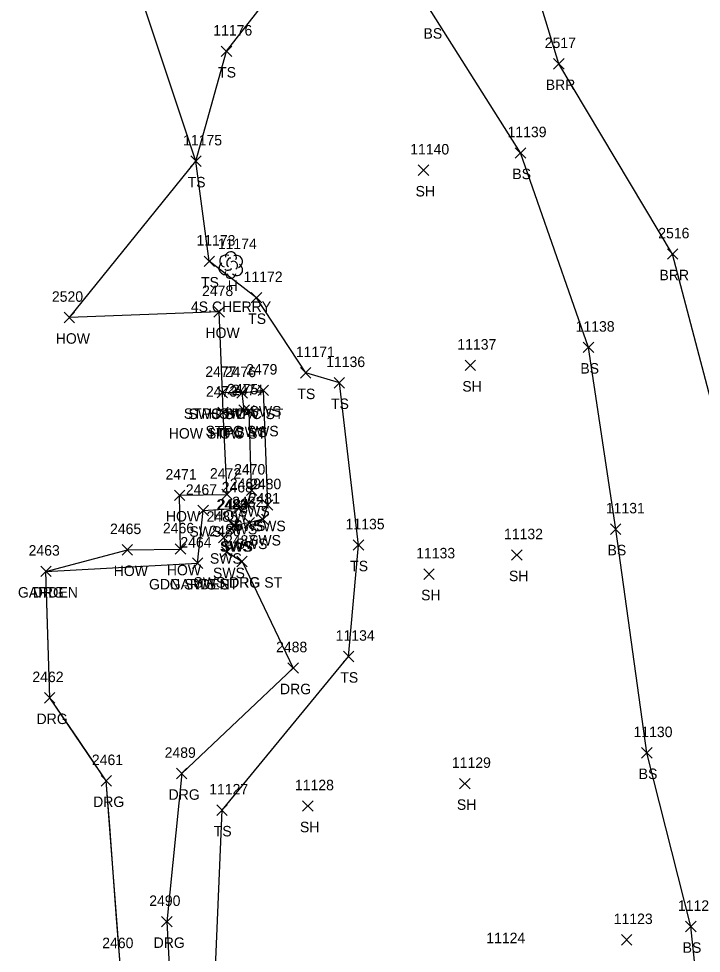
# Model space of a CAD drawing. Extents: x 1439173 to 1457902, y 641926 to 659889.
# Drawn here: x 1447787.4 to 1447917.7, y 648142.7 to 648320.9 of the extents above; entities that cross this region are included whole.
import ezdxf

# ---------------------------------------------------------------- set-up
doc = ezdxf.new("R2010")
doc.units = 0
for name, color, linetype in [('L_A', 7, 'Continuous'), ('L_C', 7, 'Continuous'), ('L_I', 7, 'Continuous'), ('L_TIC', 7, 'Continuous'), ('LABL', 7, 'Continuous'), ('LAPB', 7, 'Continuous'), ('LBC', 7, 'Continuous'), ('LBF', 7, 'Continuous'), ('LELB', 7, 'Continuous'), ('LSOGP', 7, 'Continuous'), ('LTD', 7, 'Continuous'), ('R_A', 7, 'Continuous'), ('R_I', 7, 'Continuous'), ('R_TIC', 7, 'Continuous'), ('RDG', 7, 'Continuous'), ('RSW', 7, 'Continuous')]:
    doc.layers.add(name, color=color, linetype=linetype)

msp = doc.modelspace()

# ---------------------------------------------------------------- linework, layer by layer
at = {"layer": 'L_TIC'}
for points in [[(1447826.09, 648313.7), (1447828.09, 648315.7)], [(1447828.09, 648313.7), (1447826.09, 648315.7)], [(1447889.52, 648311.32), (1447891.52, 648313.32)], [(1447891.52, 648311.32), (1447889.52, 648313.32)], [(1447882.2, 648294.32), (1447884.2, 648296.32)], [(1447884.2, 648294.32), (1447882.2, 648296.32)], [(1447820.27, 648292.75), (1447822.27, 648294.75)], [(1447822.27, 648292.75), (1447820.27, 648294.75)], [(1447863.69, 648291.02), (1447865.69, 648293.02)], [(1447865.69, 648291.02), (1447863.69, 648293.02)], [(1447911.22, 648275.03), (1447913.22, 648277.03)], [(1447913.22, 648275.03), (1447911.22, 648277.03)], [(1447822.82, 648273.65), (1447824.82, 648275.65)], [(1447824.82, 648273.65), (1447822.82, 648275.65)], [(1447831.83, 648266.7), (1447833.83, 648268.7)], [(1447833.83, 648266.7), (1447831.83, 648268.7)], [(1447796.13, 648262.93), (1447798.13, 648264.93)], [(1447798.13, 648262.93), (1447796.13, 648264.93)], [(1447824.7, 648264.02), (1447826.7, 648266.02)], [(1447826.7, 648264.02), (1447824.7, 648266.02)], [(1447895.17, 648257.23), (1447897.17, 648259.23)], [(1447897.17, 648257.23), (1447895.17, 648259.23)], [(1447872.61, 648253.81), (1447874.61, 648255.81)], [(1447874.61, 648253.81), (1447872.61, 648255.81)], [(1447841.22, 648252.37), (1447843.22, 648254.37)], [(1447843.22, 648252.37), (1447841.22, 648254.37)], [(1447847.64, 648250.48), (1447849.64, 648252.48)], [(1447849.64, 648250.48), (1447847.64, 648252.48)], [(1447825.32, 648248.61), (1447827.32, 648250.61)], [(1447827.32, 648248.61), (1447825.32, 648250.61)], [(1447825.32, 648248.61), (1447827.32, 648250.61)], [(1447827.32, 648248.61), (1447825.32, 648250.61)], [(1447829.1, 648248.56), (1447831.1, 648250.56)], [(1447831.1, 648248.56), (1447829.1, 648250.56)], [(1447825.45, 648244.84), (1447827.45, 648246.84)], [(1447827.45, 648244.84), (1447825.45, 648246.84)], [(1447825.45, 648244.84), (1447827.45, 648246.84)], [(1447827.45, 648244.84), (1447825.45, 648246.84)], [(1447829.47, 648245.27), (1447831.47, 648247.27)], [(1447831.47, 648245.27), (1447829.47, 648247.27)], [(1447817.15, 648229.03), (1447819.15, 648231.03)], [(1447819.15, 648229.03), (1447817.15, 648231.03)], [(1447826.2, 648229.2), (1447828.2, 648231.2)], [(1447828.2, 648229.2), (1447826.2, 648231.2)], [(1447900.37, 648222.58), (1447902.37, 648224.58)], [(1447902.37, 648222.58), (1447900.37, 648224.58)], [(1447807.19, 648218.63), (1447809.19, 648220.63)], [(1447809.19, 648218.63), (1447807.19, 648220.63)], [(1447817.33, 648218.77), (1447819.33, 648220.77)], [(1447819.33, 648218.77), (1447817.33, 648220.77)], [(1447851.29, 648219.54), (1447853.29, 648221.54)], [(1447853.29, 648219.54), (1447851.29, 648221.54)], [(1447881.51, 648217.65), (1447883.51, 648219.65)], [(1447883.51, 648217.65), (1447881.51, 648219.65)], [(1447791.65, 648214.52), (1447793.65, 648216.52)], [(1447793.65, 648214.52), (1447791.65, 648216.52)], [(1447820.6, 648216.07), (1447822.6, 648218.07)], [(1447822.6, 648216.07), (1447820.6, 648218.07)], [(1447864.75, 648214), (1447866.75, 648216)], [(1447866.75, 648214), (1447864.75, 648216)], [(1447849.4, 648198.29), (1447851.4, 648200.29)], [(1447851.4, 648198.29), (1447849.4, 648200.29)], [(1447906.31, 648179.91), (1447908.31, 648181.91)], [(1447908.31, 648179.91), (1447906.31, 648181.91)], [(1447871.57, 648174.04), (1447873.57, 648176.04)], [(1447873.57, 648174.04), (1447871.57, 648176.04)], [(1447825.26, 648168.98), (1447827.26, 648170.98)], [(1447827.26, 648168.98), (1447825.26, 648170.98)], [(1447841.62, 648169.77), (1447843.62, 648171.77)], [(1447843.62, 648169.77), (1447841.62, 648171.77)], [(1447914.7, 648146.78), (1447916.7, 648148.78)], [(1447916.7, 648146.78), (1447914.7, 648148.78)], [(1447902.45, 648144.26), (1447904.45, 648146.26)], [(1447904.45, 648144.26), (1447902.45, 648146.26)]]:
    msp.add_lwpolyline(points, dxfattribs=at)
at = {"layer": 'LABL'}
msp.add_lwpolyline([(1447975.52, 648148.69), (1447981.52, 648110.97), (1447974.2, 648092.22), (1447958.64, 648075.67), (1447941.87, 648100.07), (1447936.57, 648139.24), (1447926.83, 648188.41), (1447923.24, 648233.98), (1447912.22, 648276.03), (1447890.52, 648312.32), (1447885.31, 648329.49), (1447844.46, 648358.6), (1447883.24, 648371.65), (1447915.86, 648376.25), (1447938.91, 648380.03), (1447948.39, 648332.97), (1447948.3, 648332.92), (1447954.84, 648284.4)], dxfattribs=at)
at = {"layer": 'LAPB'}
msp.add_lwpolyline([(1447792.65, 648215.52), (1447821.6, 648217.07)], dxfattribs=at)
at = {"layer": 'LBC'}
msp.add_lwpolyline([(1447808.19, 648219.63), (1447818.33, 648219.77), (1447818.15, 648230.03), (1447827.2, 648230.2), (1447826.45, 648245.84), (1447826.32, 648249.61), (1447825.7, 648265.02), (1447797.13, 648263.93)], dxfattribs=at)
at = {"layer": 'LBF'}
for points in [[(1447830.1, 648249.56), (1447826.32, 648249.61)], [(1447826.45, 648245.84), (1447830.47, 648246.27)]]:
    msp.add_lwpolyline(points, dxfattribs=at)
at = {"layer": 'LELB'}
for points in [[(1447948.66, 648059.36), (1447926.41, 648053.33), (1447891.46, 648047.11), (1447863.43, 648042.99), (1447838.8, 648055.7), (1447830.08, 648068.33), (1447823.25, 648098.35), (1447824.6, 648130.92), (1447826.26, 648169.98), (1447850.4, 648199.29), (1447852.29, 648220.54), (1447848.64, 648251.48), (1447842.22, 648253.37), (1447832.83, 648267.7), (1447823.82, 648274.65), (1447821.27, 648293.75), (1447827.09, 648314.7), (1447838.18, 648328.91), (1447846.62, 648343.8), (1447843.4, 648351.49), (1447804.36, 648349.3)], [(1447925.77, 648058.24), (1447929.14, 648088.66), (1447919.16, 648115.38), (1447915.7, 648147.78), (1447907.31, 648180.91), (1447901.37, 648223.58), (1447896.17, 648258.23), (1447883.2, 648295.32), (1447866.25, 648322.11), (1447854.43, 648340.12), (1447846.62, 648343.8), (1447805.14, 648342.06)]]:
    msp.add_lwpolyline(points, dxfattribs=at)
at = {"layer": 'LSOGP'}
msp.add_lwpolyline([(1447806.79, 648140.65), (1447806.13, 648149.38), (1447805.48, 648158.11), (1447804.82, 648166.84), (1447804.17, 648175.57), (1447798.77, 648183.49), (1447793.37, 648191.4), (1447793.19, 648197.43), (1447793.01, 648203.46), (1447792.82, 648209.49), (1447792.64, 648215.52), (1447808.19, 648219.63), (1447818.33, 648219.77), (1447818.15, 648230.04), (1447827.2, 648230.2), (1447826.46, 648245.83), (1447826.32, 648249.62), (1447825.7, 648265.01), (1447797.13, 648263.93), (1447821.27, 648293.77), (1447805.14, 648342.09)], dxfattribs=at)
at = {"layer": 'LTD'}
msp.add_line((1447827.9, 648273.99), (1447827.9, 648273.99), dxfattribs=at)
msp.add_line((1447827.9, 648273.99), (1447827.9, 648273.99), dxfattribs=at)
msp.add_arc((1447827.94, 648275.43), 1.05, 335.5272, 180.9563, dxfattribs=at)
for centre, major_axis, ratio, start_param, end_param in [((1447827.1, 648274.66), (1.21, -0.51), 0.895232, 1.570796, 4.712389), ((1447827.69, 648274.45), (-0.208, -0.792), 0.645439, 3.141593, 6.283185), ((1447828.94, 648274.58), (-1.14, -0.48), 0.949671, 1.570796, 4.712389), ((1447826.81, 648273.28), (0.58, -1.04), 0.959034, 3.141593, 6.283185), ((1447828.4, 648273.83), (-0.5, 0.667), 0.989748, 3.141593, 6.283185), ((1447828.9, 648273.16), (-1.09, 0.79), 0.841452, 1.570796, 4.712389), ((1447827.9, 648272.49), (0.26, 1.06), 0.942809, 1.570796, 4.712389), ((1447827.44, 648273.24), (-0.625, -0.083), 0.423636, 0, 3.141593)]:
    msp.add_ellipse(centre, major_axis=major_axis, ratio=ratio, start_param=start_param, end_param=end_param, dxfattribs=at)
at = {"layer": 'R_TIC'}
for points in [[(1447829.1, 648248.56), (1447831.1, 648250.56)], [(1447831.1, 648248.56), (1447829.1, 648250.56)], [(1447833.13, 648249.05), (1447835.13, 648251.05)], [(1447835.13, 648249.05), (1447833.13, 648251.05)], [(1447829.47, 648245.27), (1447831.47, 648247.27)], [(1447831.47, 648245.27), (1447829.47, 648247.27)], [(1447830.41, 648245.12), (1447832.41, 648247.12)], [(1447832.41, 648245.12), (1447830.41, 648247.12)], [(1447830.9, 648229.98), (1447832.9, 648231.98)], [(1447832.9, 648229.98), (1447830.9, 648231.98)], [(1447830.06, 648227.23), (1447832.06, 648229.23)], [(1447832.06, 648227.23), (1447830.06, 648229.23)], [(1447833.94, 648227.18), (1447835.94, 648229.18)], [(1447835.94, 648227.18), (1447833.94, 648229.18)], [(1447821.65, 648226.12), (1447823.65, 648228.12)], [(1447823.65, 648226.12), (1447821.65, 648228.12)], [(1447828.51, 648226.58), (1447830.51, 648228.58)], [(1447830.51, 648226.58), (1447828.51, 648228.58)], [(1447827.45, 648223.27), (1447829.45, 648225.27)], [(1447829.45, 648223.27), (1447827.45, 648225.27)], [(1447827.68, 648223.29), (1447829.68, 648225.29)], [(1447829.68, 648223.29), (1447827.68, 648225.29)], [(1447830.45, 648223.77), (1447832.45, 648225.77)], [(1447832.45, 648223.77), (1447830.45, 648225.77)], [(1447833.03, 648224.45), (1447835.03, 648226.45)], [(1447835.03, 648224.45), (1447833.03, 648226.45)], [(1447825.57, 648220.98), (1447827.57, 648222.98)], [(1447827.57, 648220.98), (1447825.57, 648222.98)], [(1447826.15, 648218.22), (1447828.15, 648220.22)], [(1447828.15, 648218.22), (1447826.15, 648220.22)], [(1447829.07, 648216.41), (1447831.07, 648218.41)], [(1447831.07, 648216.41), (1447829.07, 648218.41)], [(1447829.07, 648216.41), (1447831.07, 648218.41)], [(1447831.07, 648216.41), (1447829.07, 648218.41)], [(1447791.65, 648214.52), (1447793.65, 648216.52)], [(1447793.65, 648214.52), (1447791.65, 648216.52)], [(1447820.6, 648216.07), (1447822.6, 648218.07)], [(1447822.6, 648216.07), (1447820.6, 648218.07)], [(1447838.82, 648196.09), (1447840.82, 648198.09)], [(1447840.82, 648196.09), (1447838.82, 648198.09)], [(1447792.37, 648190.4), (1447794.37, 648192.4)], [(1447794.37, 648190.4), (1447792.37, 648192.4)], [(1447817.56, 648175.96), (1447819.56, 648177.96)], [(1447819.56, 648175.96), (1447817.56, 648177.96)], [(1447803.16, 648174.58), (1447805.16, 648176.58)], [(1447805.16, 648174.58), (1447803.16, 648176.58)], [(1447814.71, 648147.71), (1447816.71, 648149.71)], [(1447816.71, 648147.71), (1447814.71, 648149.71)]]:
    msp.add_lwpolyline(points, dxfattribs=at)
at = {"layer": 'RDG'}
for points in [[(1447830.07, 648217.41), (1447839.82, 648197.09), (1447818.56, 648176.96), (1447815.71, 648148.71), (1447817.42, 648116.7), (1447817.39, 648116.66), (1447822.31, 648081.99), (1447826.74, 648066.41), (1447833.19, 648054.59), (1447847.63, 648042.87), (1447857.73, 648041.17), (1447891.19, 648045.8), (1447923.48, 648050.8), (1447947.17, 648055.37), (1447974.14, 648064.54)], [(1447814.09, 648028.59), (1447824.25, 648033.86), (1447821.06, 648054.4), (1447812.57, 648078.1), (1447812.73, 648078.08), (1447808.88, 648103.1), (1447806.79, 648140.66), (1447804.16, 648175.58), (1447793.37, 648191.4), (1447792.65, 648215.52)]]:
    msp.add_lwpolyline(points, dxfattribs=at)
at = {"layer": 'RSW'}
msp.add_lwpolyline([(1447821.6, 648217.07), (1447822.65, 648227.12), (1447829.51, 648227.58), (1447831.06, 648228.23), (1447831.9, 648230.98), (1447831.41, 648246.12), (1447830.47, 648246.27), (1447830.1, 648249.56), (1447834.13, 648250.05), (1447834.94, 648228.18), (1447834.03, 648225.45), (1447831.45, 648224.77), (1447828.45, 648224.27), (1447828.68, 648224.29), (1447826.57, 648221.98), (1447827.15, 648219.22), (1447830.07, 648217.41)], dxfattribs=at)

# ---------------------------------------------------------------- texts
at = {"layer": 'L_A'}
for s, p in [('BS', (1447864.69, 648317.11)), ('TS', (1447825.5, 648309.7)), ('BRR', (1447888.01, 648307.32)), ('BS', (1447881.64, 648290.32)), ('TS', (1447819.68, 648288.75)), ('SH', (1447863.18, 648287.02)), ('TS', (1447822.23, 648269.65)), ('BRR', (1447909.71, 648271.03)), ('H', (1447827.33, 648268.99)), ('TS', (1447831.24, 648262.7)), ('HOW', (1447794.52, 648258.93)), ('HOW', (1447823.09, 648260.02)), ('BS', (1447894.62, 648253.23)), ('TS', (1447840.63, 648248.37)), ('SH', (1447872.1, 648249.81)), ('TS', (1447847.04, 648246.48)), ('STPC HOW', (1447818.95, 648244.61)), ('SWS STPC ST', (1447819.84, 648244.56)), ('HOW', (1447823.7, 648244.61)), ('STPC SWS', (1447823.09, 648241.27)), ('HOW STPC ST', (1447816.08, 648240.84)), ('HOW', (1447823.84, 648240.84)), ('HOW', (1447815.54, 648225.03)), ('HOW', (1447824.58, 648225.2)), ('BS', (1447899.81, 648218.58)), ('HOW', (1447805.58, 648214.63)), ('HOW', (1447815.72, 648214.77)), ('TS', (1447850.7, 648215.54)), ('SH', (1447881, 648213.65)), ('GARDEN', (1447816.27, 648212.07)), ('GARDEN', (1447787.31, 648210.52)), ('SH', (1447864.24, 648210)), ('TS', (1447848.81, 648194.29)), ('BS', (1447905.75, 648175.91)), ('SH', (1447871.06, 648170.04)), ('TS', (1447824.67, 648164.98)), ('SH', (1447841.11, 648165.77)), ('BS', (1447914.14, 648142.78))]:
    msp.add_text(s, height=2, dxfattribs=at).set_placement(p)
at = {"layer": 'L_C'}
msp.add_text('4S.CHERRY', height=2, dxfattribs=at).set_placement((1447820.31, 648264.99))
at = {"layer": 'L_I'}
for s, p in [('11176', (1447824.58, 648317.7)), ('2517', (1447887.83, 648315.32)), ('11139', (1447880.73, 648298.32)), ('11175', (1447818.82, 648296.75)), ('11140', (1447862.15, 648295.02)), ('2516', (1447909.48, 648279.03)), ('11173', (1447821.37, 648277.65)), ('11174', (1447825.44, 648276.99)), ('11172', (1447830.37, 648270.7)), ('2478', (1447822.44, 648268.02)), ('2520', (1447793.79, 648266.93)), ('11138', (1447893.72, 648261.23)), ('11137', (1447871.15, 648257.81)), ('11171', (1447840.33, 648256.37)), ('11136', (1447846.12, 648254.48)), ('2477', (1447823.06, 648252.61)), ('2477', (1447823.06, 648252.61)), ('2476', (1447826.78, 648252.56)), ('2473', (1447823.19, 648248.84)), ('2473', (1447823.19, 648248.84)), ('2475', (1447827.21, 648249.27)), ('2471', (1447815.46, 648233.03)), ('2472', (1447823.94, 648233.2)), ('11131', (1447899.48, 648226.58)), ('11135', (1447849.83, 648223.54)), ('2465', (1447804.88, 648222.63)), ('2466', (1447814.97, 648222.77)), ('11132', (1447880.05, 648221.65)), ('2464', (1447818.3, 648220.07)), ('2463', (1447789.34, 648218.52)), ('11133', (1447863.29, 648218)), ('11134', (1447847.94, 648202.29)), ('11130', (1447904.76, 648183.91)), ('11129', (1447870.11, 648178.04)), ('11128', (1447840.16, 648173.77)), ('11127', (1447823.8, 648172.98)), ('11122', (1447913.24, 648150.78)), ('11123', (1447900.99, 648148.26)), ('11124', (1447876.67, 648144.61))]:
    msp.add_text(s, height=2, dxfattribs=at).set_placement(p)
at = {"layer": 'R_A'}
for s, p in [('SWS', (1447831.5, 648245.05)), ('SWS STPC ST', (1447819.84, 648244.56)), ('STPC SWS', (1447823.09, 648241.27)), ('SWS', (1447828.78, 648241.12)), ('SWS', (1447829.27, 648225.98)), ('SWS', (1447828.43, 648223.23)), ('SWS', (1447820.02, 648222.12)), ('SWS', (1447826.88, 648222.58)), ('SWS', (1447832.31, 648223.18)), ('SWS', (1447828.82, 648219.77)), ('SWS', (1447831.4, 648220.45)), ('SWS', (1447825.82, 648219.27)), ('SWS', (1447826.05, 648219.29)), ('SWS', (1447823.94, 648216.98)), ('SWS', (1447824.52, 648214.22)), ('GDN SWS ST', (1447812.32, 648212.07)), ('SWS DRG ST', (1447820.79, 648212.41)), ('DRG', (1447827.56, 648212.41)), ('DRG', (1447790.13, 648210.52)), ('DRG', (1447837.31, 648192.09)), ('DRG', (1447790.86, 648186.4)), ('DRG', (1447816.05, 648171.96)), ('DRG', (1447801.65, 648170.58)), ('DRG', (1447813.2, 648143.71))]:
    msp.add_text(s, height=2, dxfattribs=at).set_placement(p)
at = {"layer": 'R_I'}
for s, p in [('2476', (1447826.78, 648252.56)), ('2479', (1447830.86, 648253.05)), ('2475', (1447827.21, 648249.27)), ('2474', (1447828.15, 648249.12)), ('2470', (1447828.56, 648233.98)), ('2468', (1447826.2, 648230.58)), ('2469', (1447827.74, 648231.23)), ('2480', (1447831.6, 648231.18)), ('2467', (1447819.34, 648230.12)), ('2483', (1447825.19, 648227.27)), ('2484', (1447825.42, 648227.29)), ('2482', (1447828.19, 648227.77)), ('2481', (1447831.34, 648228.45)), ('2485', (1447823.31, 648224.98)), ('2486', (1447823.84, 648222.22)), ('2464', (1447818.3, 648220.07)), ('2487', (1447826.81, 648220.41)), ('2487', (1447826.81, 648220.41)), ('2463', (1447789.34, 648218.52)), ('2488', (1447836.56, 648200.09)), ('2462', (1447790.06, 648194.4)), ('2489', (1447815.3, 648179.96)), ('2461', (1447801.42, 648178.58)), ('2490', (1447812.36, 648151.71)), ('2460', (1447803.39, 648143.66))]:
    msp.add_text(s, height=2, dxfattribs=at).set_placement(p)

doc.saveas('drawing.dxf')
